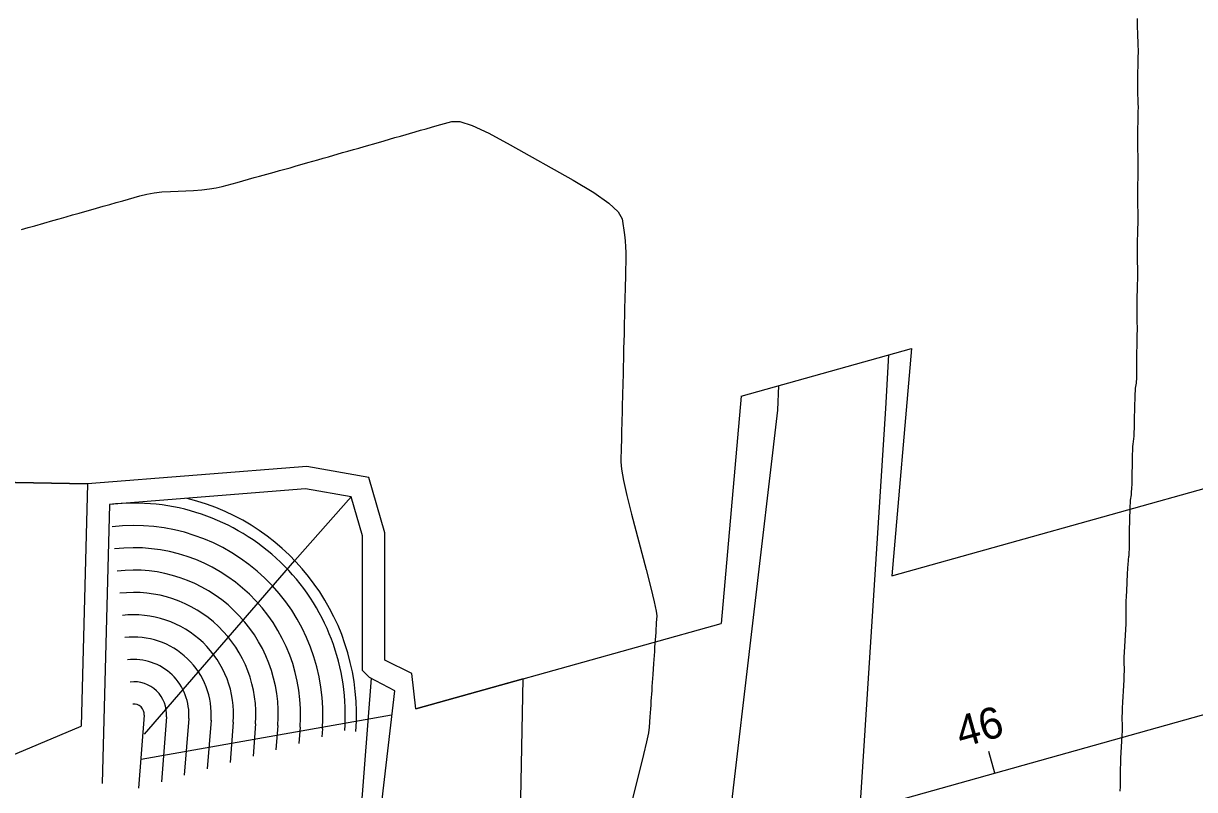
# Model space of a CAD drawing. Extents: x 1512289 to 1544686, y 552531 to 589211.
# Drawn here: x 1543120 to 1543224.9, y 587380.1 to 587448.7 of the extents above; entities that cross this region are included whole.
import ezdxf

# ---------------------------------------------------------------- set-up
doc = ezdxf.new("R2010")
doc.units = 0
for name, color, linetype in [('DR_X_Flood_Boundary', 7, 'Continuous'), ('DT_P_Break_Line', 7, 'Continuous'), ('DT_P_Contour_Minor', 7, 'Continuous'), ('DT_P_Slope_Break_Line', 7, 'Continuous'), ('GE_X_CL_20', 7, 'Continuous'), ('GK_Visualization', 7, 'Continuous'), ('RD_P_Fence', 7, 'Continuous'), ('RW_P_Const_Limits', 7, 'Continuous'), ('SC_Scratch1', 7, 'Continuous'), ('SC_Scratch2', 7, 'Continuous')]:
    doc.layers.add(name, color=color, linetype=linetype)

msp = doc.modelspace()

# ---------------------------------------------------------------- linework, layer by layer
at = {"layer": 'DR_X_Flood_Boundary'}
for points in [[(1543219.71, 587449.09), (1543219.71, 587448.63), (1543219.72, 587448.22), (1543219.73, 587447.88), (1543219.74, 587447.6), (1543219.77, 587446.92), (1543219.78, 587446.7), (1543219.78, 587446.53), (1543219.79, 587446.42), (1543219.79, 587446.37), (1543219.79, 587446.31), (1543219.79, 587446.23), (1543219.79, 587446.02), (1543219.78, 587445.7), (1543219.77, 587445.25), (1543219.75, 587443.89), (1543219.74, 587443.42), (1543219.74, 587443.01), (1543219.74, 587442.67), (1543219.75, 587442.4), (1543219.78, 587441.77), (1543219.78, 587441.5), (1543219.79, 587441.16), (1543219.78, 587440.74), (1543219.78, 587440.25), (1543219.75, 587438.85), (1543219.74, 587438.36), (1543219.74, 587437.95), (1543219.74, 587437.62), (1543219.75, 587437.36), (1543219.77, 587436.77), (1543219.78, 587436.51), (1543219.78, 587436.17), (1543219.78, 587435.75), (1543219.77, 587435.25), (1543219.74, 587433.81), (1543219.73, 587433.31), (1543219.73, 587432.9), (1543219.73, 587432.57), (1543219.74, 587432.32), (1543219.76, 587431.78), (1543219.76, 587431.53), (1543219.76, 587431.19), (1543219.76, 587430.77), (1543219.75, 587430.26), (1543219.72, 587428.78), (1543219.71, 587428.27), (1543219.71, 587427.85), (1543219.71, 587427.52), (1543219.71, 587427.29), (1543219.73, 587426.78), (1543219.73, 587426.54), (1543219.73, 587426.21), (1543219.73, 587425.78), (1543219.72, 587425.26), (1543219.69, 587423.74), (1543219.68, 587423.23), (1543219.68, 587422.8), (1543219.68, 587422.48), (1543219.68, 587422.25), (1543219.69, 587421.78), (1543219.7, 587421.55), (1543219.7, 587421.22), (1543219.69, 587420.79), (1543219.68, 587420.26), (1543219.65, 587418.71), (1543219.64, 587418.19), (1543219.64, 587417.79), (1543219.64, 587417.5), (1543219.64, 587417.33), (1543219.65, 587417.03), (1543219.65, 587416.91), (1543219.64, 587416.77), (1543219.63, 587416.62), (1543219.61, 587416.46), (1543219.55, 587416.01), (1543219.53, 587415.79), (1543219.51, 587415.46), (1543219.5, 587415.04), (1543219.49, 587414.51), (1543219.46, 587412.97), (1543219.45, 587412.44), (1543219.43, 587412.01), (1543219.41, 587411.69), (1543219.39, 587411.46), (1543219.33, 587410.99), (1543219.31, 587410.77), (1543219.29, 587410.44), (1543219.28, 587410.02), (1543219.27, 587409.5), (1543219.24, 587407.97), (1543219.23, 587407.44), (1543219.21, 587407.01), (1543219.19, 587406.69), (1543219.17, 587406.46), (1543219.1, 587405.98), (1543219.08, 587405.75), (1543219.06, 587405.42), (1543219.05, 587405), (1543219.04, 587404.48), (1543219.01, 587402.96), (1543219, 587402.45), (1543218.99, 587402.05), (1543218.99, 587401.77), (1543218.99, 587401.6), (1543218.98, 587401.3), (1543218.98, 587401.19), (1543218.97, 587401.08), (1543218.96, 587400.99), (1543218.95, 587400.9), (1543218.92, 587400.67), (1543218.9, 587400.52), (1543218.89, 587400.26), (1543218.86, 587399.87), (1543218.83, 587399.37), (1543218.75, 587397.87), (1543218.72, 587397.35), (1543218.7, 587396.93), (1543218.7, 587396.6), (1543218.7, 587396.37), (1543218.71, 587395.87), (1543218.71, 587395.64), (1543218.7, 587395.31), (1543218.69, 587394.89), (1543218.66, 587394.38), (1543218.58, 587392.87), (1543218.55, 587392.35), (1543218.53, 587391.93), (1543218.52, 587391.61), (1543218.52, 587391.37), (1543218.54, 587390.88), (1543218.54, 587390.65), (1543218.53, 587390.32), (1543218.51, 587389.9), (1543218.49, 587389.38), (1543218.41, 587387.88), (1543218.38, 587387.36), (1543218.36, 587386.94), (1543218.35, 587386.61), (1543218.35, 587386.38), (1543218.36, 587385.89), (1543218.36, 587385.65), (1543218.36, 587385.33), (1543218.34, 587384.9), (1543218.31, 587384.39), (1543218.23, 587382.88), (1543218.21, 587382.36), (1543218.19, 587381.94), (1543218.18, 587381.61), (1543218.18, 587381.38), (1543218.19, 587380.89), (1543218.19, 587380.66), (1543218.18, 587380.33), (1543218.16, 587379.91)], [(1543119.85, 587430.21), (1543120.45, 587430.38), (1543121.05, 587430.55), (1543122.64, 587431), (1543123.23, 587431.17), (1543123.83, 587431.34), (1543124.42, 587431.51), (1543125.01, 587431.67), (1543126.57, 587432.12), (1543127.16, 587432.29), (1543127.74, 587432.45), (1543128.33, 587432.62), (1543128.91, 587432.78), (1543130.45, 587433.22), (1543131.06, 587433.37), (1543131.71, 587433.48), (1543132.41, 587433.57), (1543133.17, 587433.62), (1543135.24, 587433.71), (1543135.99, 587433.76), (1543136.66, 587433.84), (1543137.27, 587433.94), (1543137.81, 587434.06), (1543139.15, 587434.43), (1543139.66, 587434.57), (1543140.16, 587434.71), (1543140.66, 587434.85), (1543141.15, 587434.98), (1543142.47, 587435.34), (1543142.95, 587435.48), (1543143.42, 587435.61), (1543143.88, 587435.74), (1543144.33, 587435.87), (1543145.49, 587436.2), (1543145.93, 587436.33), (1543146.38, 587436.46), (1543146.84, 587436.59), (1543147.32, 587436.72), (1543148.59, 587437.09), (1543149.07, 587437.23), (1543149.55, 587437.36), (1543150.03, 587437.5), (1543150.52, 587437.64), (1543151.81, 587438.01), (1543152.3, 587438.15), (1543152.78, 587438.29), (1543153.27, 587438.43), (1543153.76, 587438.57), (1543155.07, 587438.95), (1543155.56, 587439.09), (1543156.06, 587439.23), (1543156.55, 587439.37), (1543157.05, 587439.51), (1543158.37, 587439.89), (1543159.07, 587439.87), (1543160.18, 587439.51), (1543161.68, 587438.82), (1543163.59, 587437.79), (1543169.22, 587434.62), (1543171.08, 587433.51), (1543172.43, 587432.56), (1543173.27, 587431.78), (1543173.6, 587431.16), (1543173.81, 587429.72), (1543173.88, 587429.19), (1543173.92, 587428.66), (1543173.94, 587428.14), (1543173.94, 587427.63), (1543173.91, 587426.28), (1543173.9, 587425.78), (1543173.88, 587425.27), (1543173.87, 587424.76), (1543173.86, 587424.26), (1543173.83, 587422.91), (1543173.81, 587422.4), (1543173.8, 587421.9), (1543173.79, 587421.39), (1543173.78, 587420.88), (1543173.74, 587419.53), (1543173.73, 587419.03), (1543173.72, 587418.52), (1543173.7, 587418.02), (1543173.69, 587417.51), (1543173.66, 587416.16), (1543173.65, 587415.66), (1543173.63, 587415.15), (1543173.62, 587414.65), (1543173.61, 587414.14), (1543173.58, 587412.79), (1543173.56, 587412.29), (1543173.55, 587411.78), (1543173.54, 587411.28), (1543173.53, 587410.77), (1543173.49, 587409.42), (1543173.54, 587408.75), (1543173.72, 587407.74), (1543174.02, 587406.39), (1543174.45, 587404.71), (1543175.76, 587399.77), (1543176.19, 587398.12), (1543176.49, 587396.88), (1543176.67, 587396.04), (1543176.72, 587395.61), (1543176.67, 587394.99), (1543176.66, 587394.74), (1543176.64, 587394.46), (1543176.62, 587394.14), (1543176.59, 587393.79), (1543176.52, 587392.8), (1543176.5, 587392.43), (1543176.47, 587392.07), (1543176.45, 587391.7), (1543176.42, 587391.34), (1543176.36, 587390.37), (1543176.33, 587390.01), (1543176.31, 587389.65), (1543176.28, 587389.29), (1543176.26, 587388.94), (1543176.19, 587387.99), (1543176.17, 587387.63), (1543176.15, 587387.28), (1543176.12, 587386.93), (1543176.1, 587386.58), (1543176.04, 587385.65), (1543175.96, 587385.15), (1543175.8, 587384.33), (1543175.53, 587383.19), (1543175.17, 587381.74), (1543174.09, 587377.47)]]:
    msp.add_lwpolyline(points, dxfattribs=at)
at = {"layer": 'DT_P_Break_Line'}
msp.add_lwpolyline([(1543163.06, 587360.24), (1543158.5, 587372.57), (1543151.72, 587375.59), (1543153.27, 587388.9), (1543151.01, 587390.11), (1543150.36, 587390.72), (1543150.36, 587402.78), (1543149.35, 587406.26), (1543145.28, 587406.98), (1543127.72, 587405.59), (1543127.07, 587380.6)], dxfattribs=at)
msp.add_arc((1543129.91, 587386.79), 19.92, 355.6111, 76.1603, dxfattribs=at)
at = {"layer": 'DT_P_Contour_Minor'}
for p, q in [((1543151.14, 587390.04), (1543147.65, 587344.53)), ((1543130.83, 587386.72), (1543130.32, 587380.19)), ((1543132.82, 587386.57), (1543132.37, 587380.76)), ((1543134.81, 587386.42), (1543134.42, 587381.34)), ((1543136.81, 587386.27), (1543136.47, 587381.91)), ((1543138.8, 587386.11), (1543138.52, 587382.48)), ((1543140.8, 587385.96), (1543140.57, 587383.06)), ((1543142.79, 587385.81), (1543142.62, 587383.63)), ((1543144.78, 587385.65), (1543144.67, 587384.2)), ((1543146.78, 587385.5), (1543146.72, 587384.77))]:
    msp.add_line(p, q, dxfattribs=at)
for radius in [18.92, 16.92, 14.92, 12.92, 10.92, 8.92, 6.92, 4.92, 2.92, 0.923]:
    msp.add_arc((1543129.91, 587386.79), radius, 355.6111, 96.6434, dxfattribs=at)
at = {"layer": 'DT_P_Slope_Break_Line'}
for p, q in [((1543144.3, 587400.57), (1543149.35, 587406.26)), ((1543130.86, 587385.02), (1543144.3, 587400.57)), ((1543130.56, 587382.79), (1543152.97, 587386.75))]:
    msp.add_line(p, q, dxfattribs=at)
at = {"layer": 'GE_X_CL_20'}
for p, q in [((1541212.25, 586824.18), (1543339.29, 587418.51)), ((1543206.97, 587381.53), (1543206.43, 587383.46))]:
    msp.add_line(p, q, dxfattribs=at)
msp.add_arc((1537339.33, 588021.26), 5927.22, 346.145191, 0.622804, dxfattribs=at)
at = {"layer": 'GK_Visualization'}
msp.add_line((1541212.25, 586824.18), (1543339.29, 587418.51), dxfattribs=at)
msp.add_arc((1537339.33, 588021.26), 5927.22, 346.145191, 0.622804, dxfattribs=at)
msp.add_arc((1537339.33, 588021.26), 5927.22, 346.145191, 0.622804, dxfattribs=at)
at = {"layer": 'RD_P_Fence'}
for points in [[(1543189.61, 587336.51), (1543194.65, 587374.22), (1543197.22, 587414.18), (1543197.48, 587418.99)], [(1543179.62, 587333.76), (1543183.18, 587376.91), (1543187.56, 587414.02), (1543187.65, 587416.24)]]:
    msp.add_lwpolyline(points, dxfattribs=at)
at = {"layer": 'RW_P_Const_Limits'}
for p, q in [((1543184.26, 587415.29), (1543199.51, 587419.55)), ((1543199.51, 587419.55), (1543197.74, 587399.2)), ((1543184.26, 587415.29), (1543182.49, 587394.94)), ((1543197.74, 587399.2), (1543239.53, 587410.88)), ((1543080.42, 587408.27), (1543125.76, 587407.44)), ((1543155.14, 587387.3), (1543182.49, 587394.94))]:
    msp.add_line(p, q, dxfattribs=at)
msp.add_lwpolyline([(1543155.14, 587387.3), (1543154.8, 587390.45), (1543152.36, 587391.66), (1543152.36, 587403.06), (1543150.93, 587408.01), (1543145.38, 587408.99), (1543125.76, 587407.44)], dxfattribs=at)
at = {"layer": 'SC_Scratch1'}
for points in [[(1543125.76, 587407.44), (1543125.2, 587385.73)], [(1543090.78, 587371.23), (1543125.2, 587385.73)]]:
    msp.add_lwpolyline(points, dxfattribs=at)
at = {"layer": 'SC_Scratch2'}
for p, q in [((1543080.42, 587408.27), (1543125.76, 587407.44)), ((1543125.76, 587407.44), (1543080.42, 587408.27)), ((1543155.14, 587387.3), (1543164.74, 587389.98)), ((1543164.74, 587389.98), (1543155.14, 587387.3)), ((1543164.02, 587349.29), (1543164.74, 587389.98)), ((1543164.02, 587349.29), (1543164.74, 587389.98))]:
    msp.add_line(p, q, dxfattribs=at)
msp.add_lwpolyline([(1543155.14, 587387.3), (1543154.8, 587390.45), (1543152.36, 587391.66), (1543152.36, 587403.06), (1543150.93, 587408.01), (1543145.38, 587408.99), (1543125.76, 587407.44)], dxfattribs=at)
msp.add_lwpolyline([(1543155.14, 587387.3), (1543154.8, 587390.45), (1543152.36, 587391.66), (1543152.36, 587403.06), (1543150.93, 587408.01), (1543145.38, 587408.99), (1543125.76, 587407.44)], dxfattribs=at)

# ---------------------------------------------------------------- texts
at = {"layer": 'GE_X_CL_20'}
msp.add_text('46', height=2.8, rotation=15.6111, dxfattribs=at).set_placement((1543203.95, 587383.8))

doc.saveas('drawing.dxf')
